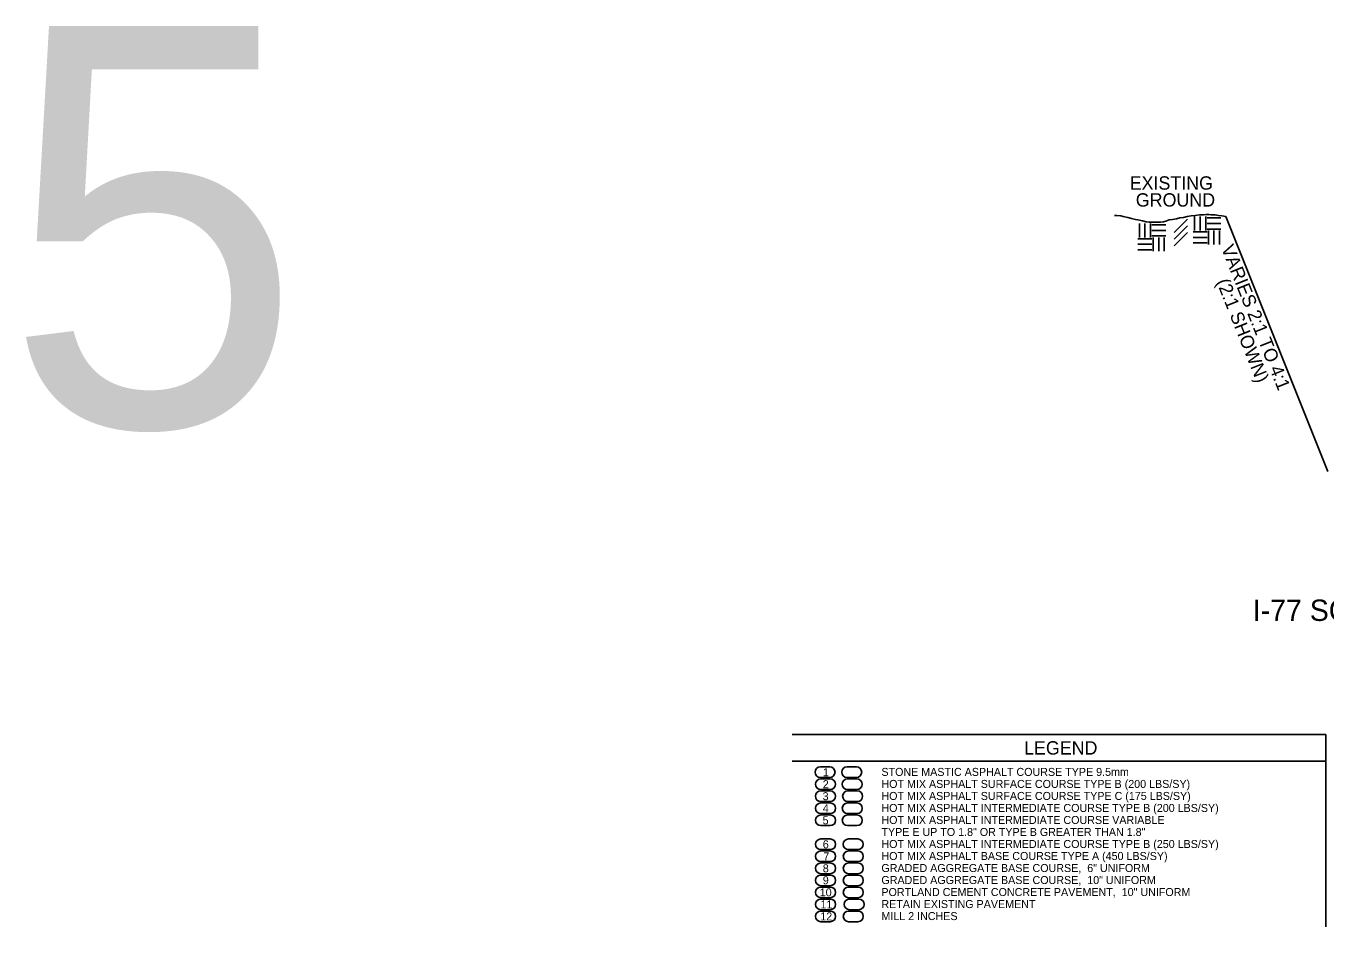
# Model space of a CAD drawing. Extents: x 2003207 to 2014043, y 843846 to 860154.
# Drawn here: x 2013558.3 to 2013655.7, y 844446 to 844513.5 of the extents above; entities that cross this region are included whole.
import ezdxf

# ---------------------------------------------------------------- set-up
doc = ezdxf.new("R2010")
doc.units = 0
for name, color, linetype in [('RD_EX_Road', 7, 'Continuous'), ('RD_EX_Road_txCode', 7, 'Continuous'), ('RD_QTY_ConcPave', 7, 'Continuous'), ('RD_QTY_Intermediate', 7, 'Continuous'), ('RD_QTY_Milling', 7, 'Continuous'), ('RD_QTY_PermVeg', 7, 'Continuous'), ('RD_QTY_Surf_Course', 7, 'Continuous'), ('RD_SHT_Bndy', 7, 'Continuous'), ('RD_SHT_TX', 7, 'Continuous'), ('RD_TX_Misc2', 7, 'Continuous'), ('RD_TX_TypSect', 7, 'Continuous'), ('RD_XS_ExGround', 7, 'Continuous')]:
    doc.layers.add(name, color=color, linetype=linetype)

msp = doc.modelspace()

# ---------------------------------------------------------------- linework, layer by layer
at = {"layer": 'RD_EX_Road'}
for p, q in [((2013620.723, 844448.087), (2013620.023, 844448.087)), ((2013620.023, 844447.287), (2013620.723, 844447.287)), ((2013620.661, 844447.187), (2013619.961, 844447.187)), ((2013619.961, 844446.387), (2013620.661, 844446.387))]:
    msp.add_line(p, q, dxfattribs=at)
for centre, start, end in [((2013620.023, 844447.687), 90, 270), ((2013620.723, 844447.687), 270, 90), ((2013619.961, 844446.787), 90, 270), ((2013620.661, 844446.787), 270, 90)]:
    msp.add_arc(centre, 0.4, start, end, dxfattribs=at)
at = {"layer": 'RD_QTY_ConcPave'}
for p, q in [((2013620.661, 844450.787), (2013619.961, 844450.787)), ((2013619.961, 844449.987), (2013620.661, 844449.987)), ((2013620.661, 844449.887), (2013619.961, 844449.887)), ((2013619.961, 844449.087), (2013620.661, 844449.087)), ((2013620.661, 844448.987), (2013619.961, 844448.987)), ((2013619.961, 844448.187), (2013620.661, 844448.187))]:
    msp.add_line(p, q, dxfattribs=at)
for centre, start, end in [((2013619.961, 844450.387), 90, 270), ((2013620.661, 844450.387), 270, 90), ((2013619.961, 844449.487), 90, 270), ((2013620.661, 844449.487), 270, 90), ((2013619.961, 844448.587), 90, 270), ((2013620.661, 844448.587), 270, 90)]:
    msp.add_arc(centre, 0.4, start, end, dxfattribs=at)
at = {"layer": 'RD_QTY_Intermediate'}
for p, q in [((2013620.582, 844455.287), (2013619.882, 844455.287)), ((2013619.882, 844454.487), (2013620.582, 844454.487)), ((2013620.582, 844454.387), (2013619.882, 844454.387)), ((2013619.882, 844453.587), (2013620.582, 844453.587)), ((2013620.65, 844452.587), (2013619.95, 844452.587)), ((2013619.95, 844451.787), (2013620.65, 844451.787)), ((2013620.661, 844451.687), (2013619.961, 844451.687)), ((2013619.961, 844450.887), (2013620.661, 844450.887))]:
    msp.add_line(p, q, dxfattribs=at)
for centre, start, end in [((2013619.882, 844454.887), 90, 270), ((2013620.582, 844454.887), 270, 90), ((2013619.882, 844453.987), 90, 270), ((2013620.582, 844453.987), 270, 90), ((2013619.95, 844452.187), 90, 270), ((2013620.65, 844452.187), 270, 90), ((2013619.961, 844451.287), 90, 270), ((2013620.661, 844451.287), 270, 90)]:
    msp.add_arc(centre, 0.4, start, end, dxfattribs=at)
at = {"layer": 'RD_QTY_Milling'}
for p, q in [((2013620.661, 844447.187), (2013619.961, 844447.187)), ((2013619.961, 844446.387), (2013620.661, 844446.387))]:
    msp.add_line(p, q, dxfattribs=at)
for centre, start, end in [((2013619.961, 844446.787), 90, 270), ((2013620.661, 844446.787), 270, 90)]:
    msp.add_arc(centre, 0.4, start, end, dxfattribs=at)
at = {"layer": 'RD_QTY_PermVeg'}
msp.add_line((2013655.875, 844480.119), (2013648.232, 844499.226), dxfattribs=at)
at = {"layer": 'RD_QTY_Surf_Course'}
for p, q in [((2013620.542, 844457.987), (2013619.842, 844457.987)), ((2013619.842, 844457.187), (2013620.542, 844457.187)), ((2013620.576, 844457.087), (2013619.876, 844457.087)), ((2013619.876, 844456.287), (2013620.576, 844456.287)), ((2013620.61, 844456.187), (2013619.91, 844456.187)), ((2013619.91, 844455.387), (2013620.61, 844455.387))]:
    msp.add_line(p, q, dxfattribs=at)
for centre, start, end in [((2013619.842, 844457.587), 90, 270), ((2013620.542, 844457.587), 270, 90), ((2013619.876, 844456.687), 90, 270), ((2013620.576, 844456.687), 270, 90), ((2013619.91, 844455.787), 90, 270), ((2013620.61, 844455.787), 270, 90)]:
    msp.add_arc(centre, 0.4, start, end, dxfattribs=at)
at = {"layer": 'RD_SHT_Bndy'}
for p, q in [((2013655.721, 844460.41), (2013615.721, 844460.41)), ((2013655.721, 844458.41), (2013655.721, 844460.41)), ((2013655.721, 844458.41), (2013615.721, 844458.41)), ((2013655.721, 844445.992), (2013655.721, 844458.41))]:
    msp.add_line(p, q, dxfattribs=at)
at = {"layer": 'RD_TX_Misc2'}
for p, q in [((2013617.842, 844457.987), (2013618.542, 844457.987)), ((2013619.842, 844457.987), (2013620.542, 844457.987)), ((2013617.842, 844457.187), (2013618.542, 844457.187)), ((2013617.876, 844457.087), (2013618.576, 844457.087)), ((2013619.842, 844457.187), (2013620.542, 844457.187)), ((2013619.876, 844457.087), (2013620.576, 844457.087)), ((2013617.871, 844456.187), (2013618.571, 844456.187)), ((2013617.876, 844456.287), (2013618.576, 844456.287)), ((2013619.876, 844456.287), (2013620.576, 844456.287)), ((2013619.91, 844456.187), (2013620.61, 844456.187)), ((2013617.871, 844455.387), (2013618.571, 844455.387)), ((2013617.882, 844455.287), (2013618.582, 844455.287)), ((2013619.882, 844455.287), (2013620.582, 844455.287)), ((2013619.91, 844455.387), (2013620.61, 844455.387)), ((2013617.882, 844454.487), (2013618.582, 844454.487)), ((2013617.882, 844454.387), (2013618.582, 844454.387)), ((2013619.882, 844454.487), (2013620.582, 844454.487)), ((2013619.882, 844454.387), (2013620.582, 844454.387)), ((2013617.882, 844453.587), (2013618.582, 844453.587)), ((2013619.882, 844453.587), (2013620.582, 844453.587)), ((2013617.882, 844452.587), (2013618.582, 844452.587)), ((2013619.95, 844452.587), (2013620.65, 844452.587)), ((2013617.882, 844451.787), (2013618.582, 844451.787)), ((2013617.882, 844451.687), (2013618.582, 844451.687)), ((2013619.95, 844451.787), (2013620.65, 844451.787)), ((2013619.961, 844451.687), (2013620.661, 844451.687)), ((2013617.882, 844450.887), (2013618.582, 844450.887)), ((2013617.882, 844450.787), (2013618.582, 844450.787)), ((2013619.961, 844450.887), (2013620.661, 844450.887)), ((2013619.961, 844450.787), (2013620.661, 844450.787)), ((2013617.882, 844449.987), (2013618.582, 844449.987)), ((2013617.882, 844449.887), (2013618.582, 844449.887)), ((2013619.961, 844449.987), (2013620.661, 844449.987)), ((2013619.961, 844449.887), (2013620.661, 844449.887)), ((2013617.882, 844449.087), (2013618.582, 844449.087)), ((2013617.882, 844448.987), (2013618.582, 844448.987)), ((2013619.961, 844449.087), (2013620.661, 844449.087)), ((2013619.961, 844448.987), (2013620.661, 844448.987)), ((2013617.882, 844448.187), (2013618.582, 844448.187)), ((2013617.882, 844448.087), (2013618.582, 844448.087)), ((2013617.882, 844447.287), (2013618.582, 844447.287)), ((2013619.961, 844448.187), (2013620.661, 844448.187)), ((2013620.023, 844448.087), (2013620.723, 844448.087)), ((2013620.023, 844447.287), (2013620.723, 844447.287)), ((2013617.882, 844447.187), (2013618.582, 844447.187)), ((2013617.882, 844446.387), (2013618.582, 844446.387)), ((2013619.961, 844447.187), (2013620.661, 844447.187)), ((2013619.961, 844446.387), (2013620.661, 844446.387))]:
    msp.add_line(p, q, dxfattribs=at)
for centre, start, end in [((2013617.842, 844457.587), 90, 270), ((2013618.542, 844457.587), 270, 90), ((2013619.842, 844457.587), 90, 270), ((2013620.542, 844457.587), 270, 90), ((2013617.876, 844456.687), 90, 270), ((2013618.576, 844456.687), 270, 90), ((2013619.876, 844456.687), 90, 270), ((2013620.576, 844456.687), 270, 90), ((2013617.871, 844455.787), 90, 270), ((2013618.571, 844455.787), 270, 90), ((2013619.91, 844455.787), 90, 270), ((2013620.61, 844455.787), 270, 90), ((2013617.882, 844454.887), 90, 270), ((2013618.582, 844454.887), 270, 90), ((2013619.882, 844454.887), 90, 270), ((2013620.582, 844454.887), 270, 90), ((2013617.882, 844453.987), 90, 270), ((2013618.582, 844453.987), 270, 90), ((2013619.882, 844453.987), 90, 270), ((2013620.582, 844453.987), 270, 90), ((2013617.882, 844452.187), 90, 270), ((2013618.582, 844452.187), 270, 90), ((2013619.95, 844452.187), 90, 270), ((2013620.65, 844452.187), 270, 90), ((2013617.882, 844451.287), 90, 270), ((2013618.582, 844451.287), 270, 90), ((2013619.961, 844451.287), 90, 270), ((2013620.661, 844451.287), 270, 90), ((2013617.882, 844450.387), 90, 270), ((2013618.582, 844450.387), 270, 90), ((2013619.961, 844450.387), 90, 270), ((2013620.661, 844450.387), 270, 90), ((2013617.882, 844449.487), 90, 270), ((2013618.582, 844449.487), 270, 90), ((2013619.961, 844449.487), 90, 270), ((2013620.661, 844449.487), 270, 90), ((2013617.882, 844448.587), 90, 270), ((2013618.582, 844448.587), 270, 90), ((2013619.961, 844448.587), 90, 270), ((2013620.661, 844448.587), 270, 90), ((2013617.882, 844447.687), 90, 270), ((2013618.582, 844447.687), 270, 90), ((2013620.023, 844447.687), 90, 270), ((2013620.723, 844447.687), 270, 90), ((2013617.882, 844446.787), 90, 270), ((2013618.582, 844446.787), 270, 90), ((2013619.961, 844446.787), 90, 270), ((2013620.661, 844446.787), 270, 90)]:
    msp.add_arc(centre, 0.4, start, end, dxfattribs=at)
at = {"layer": 'RD_XS_ExGround'}
for p, q in [((2013644.366, 844498.02), (2013645.366, 844499.02)), ((2013645.889, 844499.21), (2013645.889, 844498.169)), ((2013646.306, 844499.21), (2013646.306, 844498.169)), ((2013646.722, 844499.21), (2013646.722, 844498.169)), ((2013646.819, 844499.114), (2013647.86, 844499.114)), ((2013641.753, 844498.692), (2013641.753, 844497.65)), ((2013642.169, 844498.692), (2013642.169, 844497.65)), ((2013642.586, 844498.692), (2013642.586, 844497.65)), ((2013642.682, 844498.595), (2013643.724, 844498.595)), ((2013642.682, 844498.178), (2013643.724, 844498.178)), ((2013644.366, 844497.52), (2013645.366, 844498.52)), ((2013644.366, 844497.02), (2013645.366, 844498.02)), ((2013645.777, 844498.072), (2013646.819, 844498.072)), ((2013646.819, 844498.697), (2013647.86, 844498.697)), ((2013646.819, 844498.28), (2013647.86, 844498.28)), ((2013646.923, 844498.176), (2013646.923, 844497.134)), ((2013647.339, 844498.176), (2013647.339, 844497.134)), ((2013647.756, 844498.176), (2013647.756, 844497.134)), ((2013641.641, 844497.553), (2013642.682, 844497.553)), ((2013641.641, 844497.137), (2013642.682, 844497.137)), ((2013642.682, 844497.762), (2013643.724, 844497.762)), ((2013642.787, 844497.658), (2013642.787, 844496.616)), ((2013643.203, 844497.658), (2013643.203, 844496.616)), ((2013643.62, 844497.658), (2013643.62, 844496.616)), ((2013645.777, 844497.655), (2013646.819, 844497.655)), ((2013645.777, 844497.239), (2013646.819, 844497.239)), ((2013641.641, 844496.72), (2013642.682, 844496.72))]:
    msp.add_line(p, q, dxfattribs=at)
msp.add_lwpolyline([(2013639.894, 844499.299), (2013640.069, 844499.299), (2013640.362, 844499.263), (2013640.545, 844499.226), (2013640.875, 844499.153), (2013641.167, 844499.079), (2013641.46, 844499.006), (2013641.643, 844498.97), (2013641.973, 844498.896), (2013642.265, 844498.823), (2013642.485, 844498.786), (2013642.668, 844498.786), (2013642.888, 844498.786), (2013643.107, 844498.786), (2013643.327, 844498.786), (2013643.547, 844498.823), (2013643.73, 844498.86), (2013643.986, 844498.97), (2013644.242, 844499.006), (2013644.535, 844499.043), (2013644.791, 844499.116), (2013645.047, 844499.153), (2013645.34, 844499.226), (2013645.633, 844499.263), (2013645.926, 844499.299), (2013646.255, 844499.336), (2013646.548, 844499.336), (2013646.768, 844499.373), (2013646.951, 844499.373), (2013647.134, 844499.336), (2013647.427, 844499.336), (2013647.683, 844499.299), (2013647.939, 844499.263), (2013648.232, 844499.226)], dxfattribs=at)

# ---------------------------------------------------------------- texts
at = {"layer": 'RD_EX_Road_txCode'}
for s, height, p in [('I-77 SOUTHBOUND STA. 1717+00.00 TO STA. 1757+00.00', 1.6, (2013650.242, 844468.922)), ('LEGEND', 1, (2013633.11, 844458.91)), ('STONE MASTIC ASPHALT COURSE TYPE 9.5mm', 0.6, (2013622.417, 844457.31)), ('HOT MIX ASPHALT SURFACE COURSE TYPE B (200 LBS/SY)', 0.6, (2013622.417, 844456.41)), ('HOT MIX ASPHALT SURFACE COURSE TYPE C (175 LBS/SY)', 0.6, (2013622.417, 844455.51)), ('HOT MIX ASPHALT INTERMEDIATE COURSE TYPE B (200 LBS/SY)', 0.6, (2013622.417, 844454.61)), ('HOT MIX ASPHALT INTERMEDIATE COURSE VARIABLE ', 0.6, (2013622.417, 844453.71)), ('TYPE E UP TO 1.8" OR TYPE B GREATER THAN 1.8"', 0.6, (2013622.417, 844452.81)), ('HOT MIX ASPHALT INTERMEDIATE COURSE TYPE B (250 LBS/SY)', 0.6, (2013622.417, 844451.91)), ('HOT MIX ASPHALT BASE COURSE TYPE A (450 LBS/SY)', 0.6, (2013622.417, 844451.01)), ('GRADED AGGREGATE BASE COURSE,  6" UNIFORM', 0.6, (2013622.417, 844450.11)), ('GRADED AGGREGATE BASE COURSE,  10" UNIFORM', 0.6, (2013622.417, 844449.21)), ('PORTLAND CEMENT CONCRETE PAVEMENT,  10" UNIFORM', 0.6, (2013622.417, 844448.31)), ('RETAIN EXISTING PAVEMENT', 0.6, (2013622.417, 844447.41)), ('MILL 2 INCHES', 0.6, (2013622.417, 844446.51))]:
    msp.add_text(s, height=height, dxfattribs=at).set_placement(p)
at = {"layer": 'RD_SHT_TX'}
msp.add_text('5', height=30, dxfattribs=at).set_placement((2013556.7, 844483.492))
at = {"layer": 'RD_TX_Misc2'}
for s, p in [('2', (2013618.022, 844456.387)), ('1', (2013618.039, 844457.287)), ('3', (2013618.011, 844455.487)), ('4', (2013618.023, 844454.587)), ('5', (2013618.011, 844453.687)), ('6', (2013618.023, 844451.887)), ('7 ', (2013618.066, 844450.987)), ('8', (2013618.023, 844450.087)), ('9', (2013618.023, 844449.187)), ('10', (2013617.796, 844448.287)), ('11', (2013617.852, 844447.387)), ('12', (2013617.835, 844446.487))]:
    msp.add_text(s, height=0.6, dxfattribs=at).set_placement(p)
at = {"layer": 'RD_TX_TypSect'}
for s, p in [('EXISTING', (2013641.026, 844501.231)), ('GROUND', (2013641.483, 844499.963))]:
    msp.add_text(s, height=1, dxfattribs=at).set_placement(p)
for s, p in [('VARIES 2:1 TO 4:1', (2013647.863, 844496.868)), ('(2:1 SHOWN)', (2013647.51, 844494.335))]:
    msp.add_text(s, height=1, rotation=291.80141, dxfattribs=at).set_placement(p)

doc.saveas('drawing.dxf')
